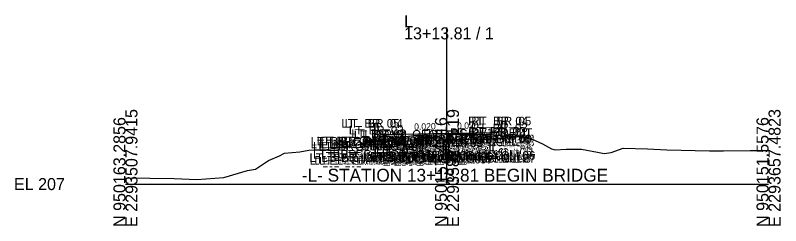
# Model space of a CAD drawing. Extents: x -26 to 7053, y -10 to 7035.
# Drawn here: x 1124.3 to 1302.8, y -9.7 to 39.3 of the extents above; entities that cross this region are included whole.
import ezdxf

# ---------------------------------------------------------------- set-up
doc = ezdxf.new("R2010")
doc.units = 0
for name, color, linetype in [('Default', 7, 'Continuous'), ('Exist Cross Section Cell', 7, 'Continuous'), ('Exist XS Center Line Elevation Label', 7, 'Continuous'), ('Exist XS Ground Line', 7, 'Continuous'), ('Prop CMT Concrete Structures', 7, 'Continuous'), ('Prop XS SE Text', 7, 'Continuous'), ('Prop XSC Text', 7, 'Continuous')]:
    doc.layers.add(name, color=color, linetype=linetype)

msp = doc.modelspace()

# ---------------------------------------------------------------- linework, layer by layer
at = {"layer": 'Exist Cross Section Cell'}
for p, q in [((1225, 0), (1225, 36.52)), ((1150, 0), (1225, 0)), ((1225, 0), (1300, 0))]:
    msp.add_line(p, q, dxfattribs=at)
at = {"layer": 'Exist XS Ground Line'}
for p, q in [((1209.34, 10.28), (1217.21, 11.35)), ((1217.21, 11.35), (1224.47, 11.59)), ((1224.47, 11.59), (1224.86, 11.6)), ((1224.86, 11.6), (1227.47, 11.61)), ((1227.47, 11.61), (1233.21, 11.65)), ((1233.21, 11.65), (1235.54, 11.47)), ((1235.54, 11.47), (1244.01, 10.82)), ((1244.01, 10.82), (1247.29, 9.39)), ((1198.44, 8.31), (1205.5, 9.31)), ((1205.5, 9.31), (1206.72, 9.7)), ((1206.72, 9.7), (1209.02, 10.23)), ((1209.02, 10.23), (1209.34, 10.28)), ((1247.29, 9.39), (1249.38, 8.18)), ((1185.91, 6.61), (1187.08, 7.19)), ((1187.08, 7.19), (1190.67, 7.5)), ((1190.67, 7.5), (1192.75, 7.88)), ((1192.75, 7.88), (1196.43, 7.98)), ((1196.43, 7.98), (1197.01, 8.06)), ((1197.01, 8.06), (1198.44, 8.31)), ((1249.38, 8.18), (1250.25, 7.99)), ((1250.25, 7.99), (1252.78, 8.16)), ((1252.78, 8.16), (1256.39, 8.1)), ((1256.39, 8.1), (1260.1, 7.46)), ((1260.1, 7.46), (1261.67, 7.1)), ((1261.67, 7.1), (1263.26, 7.35)), ((1263.26, 7.35), (1266.12, 8.35)), ((1266.12, 8.35), (1271.8, 8.23)), ((1271.8, 8.23), (1276.25, 7.97)), ((1276.25, 7.97), (1286.26, 7.72)), ((1286.26, 7.72), (1289.5, 7.76)), ((1289.5, 7.76), (1295.71, 7.82)), ((1295.71, 7.82), (1300, 7.79)), ((1180.34, 3.51), (1183.38, 5.47)), ((1183.38, 5.47), (1185.91, 6.61)), ((1172.91, 1.5), (1178.43, 3.15)), ((1178.43, 3.15), (1180.34, 3.51)), ((1150, 1.46), (1161.35, 1.33)), ((1161.35, 1.33), (1166.65, 1.08)), ((1166.65, 1.08), (1172.91, 1.5))]:
    msp.add_line(p, q, dxfattribs=at)
at = {"layer": 'Prop CMT Concrete Structures'}
for points in [[(1225, 11.79), (1235, 11.99), (1237, 12.03), (1237.01, 12.28), (1237.59, 13.11), (1237.76, 14.69), (1238.5, 14.69), (1238.5, 10.56)], [(1225, 11.79), (1215, 11.59), (1209.65, 11.48), (1209.64, 11.73), (1209.06, 12.56), (1208.89, 14.15), (1208.15, 14.15), (1208.15, 9.95)], [(1225, 10.29), (1225, 11.79)], [(1225, 10.29), (1225, 11.79)], [(1208.15, 9.95), (1215, 10.09), (1225, 10.29)], [(1212.11, 10.03), (1211.27, 10.01), (1210.44, 9.99)], [(1210.44, 9.99), (1210.44, 9.34)], [(1210.44, 9.34), (1210.94, 8.84)], [(1211.61, 8.84), (1212.11, 9.34)], [(1212.11, 9.34), (1212.11, 10.03)], [(1225, 10.29), (1224.17, 10.27)], [(1224.17, 10.27), (1224.17, 9.62)], [(1224.17, 9.62), (1224.67, 9.12)], [(1224.67, 9.12), (1224.67, 7.2)], [(1238.5, 10.56), (1235, 10.49), (1225, 10.29)], [(1225, 10.29), (1225.83, 10.3)], [(1225, 5.79), (1225, 10.29)], [(1225, 5.79), (1225, 10.29)], [(1225.83, 9.62), (1225.33, 9.12)], [(1225.33, 9.12), (1225.33, 7.2)], [(1225.83, 10.3), (1225.83, 9.62)], [(1234.54, 10.48), (1235.38, 10.49), (1236.21, 10.51)], [(1234.54, 9.83), (1234.54, 10.48)], [(1235.04, 9.33), (1234.54, 9.83)], [(1235.04, 7.41), (1235.04, 9.33)], [(1236.21, 9.83), (1235.71, 9.33)], [(1235.71, 9.33), (1235.71, 7.41)], [(1236.21, 10.51), (1236.21, 9.83)], [(1210.94, 8.84), (1210.94, 6.93)], [(1211.61, 6.93), (1211.61, 8.84)], [(1224.67, 7.2), (1223.92, 6.45)], [(1225.33, 7.2), (1226.08, 6.45)], [(1234.29, 6.66), (1235.04, 7.41)], [(1235.71, 7.41), (1236.46, 6.66)], [(1210.94, 6.93), (1210.19, 6.18)], [(1210.19, 6.18), (1210.19, 5.51)], [(1210.19, 5.51), (1211.27, 5.51), (1212.36, 5.51)], [(1212.36, 6.18), (1211.61, 6.93)], [(1212.36, 5.51), (1212.36, 6.18)], [(1223.92, 6.45), (1223.92, 5.79)], [(1223.92, 5.79), (1225, 5.79)], [(1226.08, 5.79), (1225, 5.79)], [(1226.08, 6.45), (1226.08, 5.79)], [(1234.29, 5.99), (1234.29, 6.66)], [(1236.46, 5.99), (1235.38, 5.99), (1234.29, 5.99)], [(1236.46, 6.66), (1236.46, 5.99)]]:
    msp.add_lwpolyline(points, dxfattribs=at)

# ---------------------------------------------------------------- texts
at = {"layer": 'Default'}
for s, height, p in [('LT_ BR_05', 2, (1200.39, 13.15)), ('LT_ BR_04', 2, (1201.13, 13.15)), ('RT_ BR_04', 2, (1229.95, 13.69)), ('RT_ BR_05', 2, (1230.69, 13.69)), ('LT_BR_03', 2, (1202.11, 11.56)), ('LT_BR_02', 2, (1202.7, 10.73)), ('LT_BR_01', 2, (1203.27, 10.48)), ('LT_PV1_OEOT', 2, (1205.74, 10.59)), ('PV1_PGL', 2, (1219.47, 10.79)), ('RT_PV1_OEOT', 2, (1225.69, 10.99)), ('RT_BR_02', 2, (1230.02, 11.28)), ('RT_BR_01', 2, (1230.57, 11.03)), ('RT_BR_03', 2, (1230.6, 12.11)), ('LT_BR_Girder Out 02', 2, (1193.23, 8.99)), ('LT_BR_Girder Out 01', 2, (1194.63, 9.01)), ('LT_BR_Girder Out 14', 2, (1195.54, 9.03)), ('LT_BR_06', 2, (1201.16, 8.95)), ('LT_BR_Girder Mid 02', 2, (1207.35, 9.27)), ('LT_BR_Girder Mid 03', 2, (1207.35, 8.62)), ('LT_BR_07', 2, (1208.06, 9.09)), ('RT_BR_Girder Mid 02', 2, (1208.97, 9.3)), ('RT_BR_Girder Mid 03', 2, (1208.97, 8.62)), ('RT_BR_Girder Out 14', 2, (1217.93, 9.48)), ('RT_BR_Girder Out 13', 2, (1217.93, 8.83)), ('RT_BR_Girder Out 01', 2, (1218.68, 9.49)), ('RT_BR_Girder Out 02', 2, (1218.95, 9.51)), ('RT_BR_Girder Out 03', 2, (1218.95, 8.83)), ('BR_PGL', 2, (1219.83, 9.29)), ('RT_BR_07', 2, (1228.01, 9.49)), ('RT_BR_06', 2, (1231.46, 9.56)), ('LT_BR_Girder Out 03', 2, (1193.23, 8.34)), ('LT_BR_Girder Out 04', 2, (1193.73, 7.84)), ('LT_BR_Girder Out 12', 2, (1195.04, 7.84)), ('LT_BR_Girder Out 13', 2, (1195.54, 8.34)), ('LT_BR_Girder Mid 04', 2, (1207.85, 8.12)), ('RT_BR_Girder Mid 04', 2, (1208.47, 8.12)), ('RT_BR_Girder Out 12', 2, (1218.43, 8.33)), ('RT_BR_Girder Out 04', 2, (1218.45, 8.33)), ('LT_BR_Girder Out 06', 2, (1192.93, 5.18)), ('LT_BR_Girder Out 05', 2, (1193.73, 5.93)), ('LT_BR_Girder Out 11', 2, (1195.61, 5.93)), ('LT_BR_Girder Out 10', 2, (1195.71, 5.18)), ('LT_BR_Girder Mid 06', 2, (1207.05, 5.45)), ('LT_BR_Girder Mid 05', 2, (1207.85, 6.2)), ('RT_BR_Girder Mid 05', 2, (1208.47, 6.2)), ('RT_BR_Girder Mid 06', 2, (1209.17, 5.45)), ('RT_BR_Girder Out 10', 2, (1217.6, 5.66)), ('RT_BR_Girder Out 05', 2, (1218.45, 6.41)), ('RT_BR_Girder Out 11', 2, (1219, 6.41)), ('RT_BR_Girder Out 06', 2, (1219.15, 5.66)), ('LT_BR_Girder Out 07', 2, (1192.98, 4.51)), ('LT_BR_Girder Out 08', 2, (1194.06, 4.51)), ('LT_BR_Girder Out 09', 2, (1195.14, 4.51)), ('LT_BR_Girder Mid 07', 2, (1207.1, 4.79)), ('RT_BR_Girder Mid 07', 2, (1209.22, 4.79)), ('BR_Girder Mid 08', 2, (1210.87, 4.79)), ('RT_BR_Girder Out 09', 2, (1217.03, 4.99)), ('RT_BR_Girder Out 08', 2, (1218.12, 4.99)), ('RT_BR_Girder Out 07', 2, (1219.2, 4.99)), ('-', 0.0001, (1150, 0))]:
    msp.add_text(s, height=height, dxfattribs=at).set_placement(p)
at = {"layer": 'Exist Cross Section Cell'}
for s, p in [('L', (1215, 36.52)), ('13+13.81 / 1', (1215, 33.72)), ('EL 207', (1124, -1.4))]:
    msp.add_text(s, height=2.8, dxfattribs=at).set_placement(p)
for s, p in [('E 2293507.9415', (1152.8, -10)), ('E 2293582.7119', (1227.8, -10)), ('E 2293657.4823', (1302.8, -10)), ('N 950163.2856', (1150, -10)), ('N 950157.4216', (1225, -10)), ('N 950151.5576', (1300, -10))]:
    msp.add_text(s, height=2.8, rotation=90, dxfattribs=at).set_placement(p)
at = {"layer": 'Exist XS Center Line Elevation Label'}
msp.add_text('218.60', height=2, dxfattribs=at).set_placement((1220.95, 6.6))
at = {"layer": 'Prop XS SE Text'}
for p in [(1227.36, 12.83), (1217.36, 12.63)]:
    msp.add_text('0.020', height=1.5, rotation=1.1458, dxfattribs=at).set_placement(p)
at = {"layer": 'Prop XSC Text'}
msp.add_text('-L- STATION 13+13.81 BEGIN BRIDGE', height=3, dxfattribs=at).set_placement((1191.14, 0.57))

doc.saveas('drawing.dxf')
